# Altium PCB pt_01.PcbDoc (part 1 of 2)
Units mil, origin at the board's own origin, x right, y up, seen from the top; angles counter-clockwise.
Board outline 1456.69 x 1118.11 mil, 4 copper layers (Top Layer, med1, med2, Bottom Layer), stack 40.249 mil thick; 153 components, 173 nets, 567 pads, 147 vias.
Unrouted connection lines stored in the file: 22.
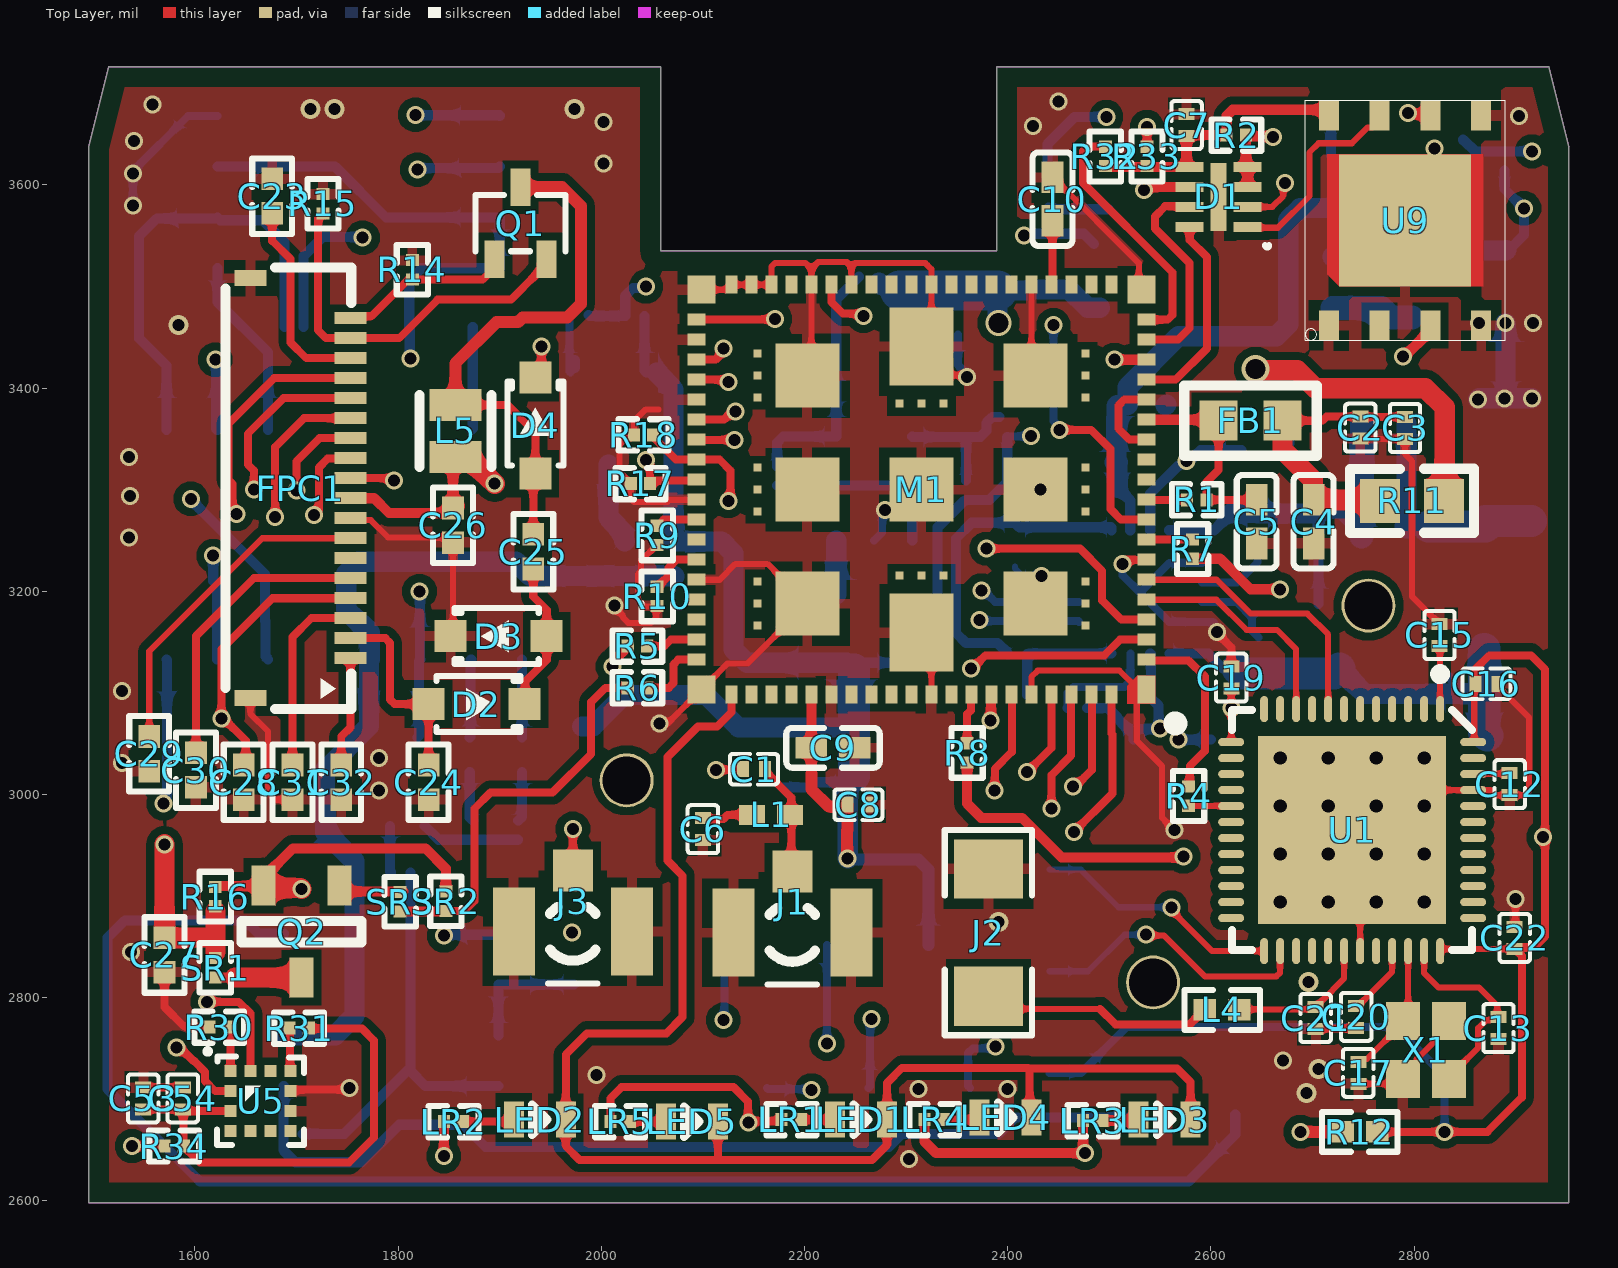
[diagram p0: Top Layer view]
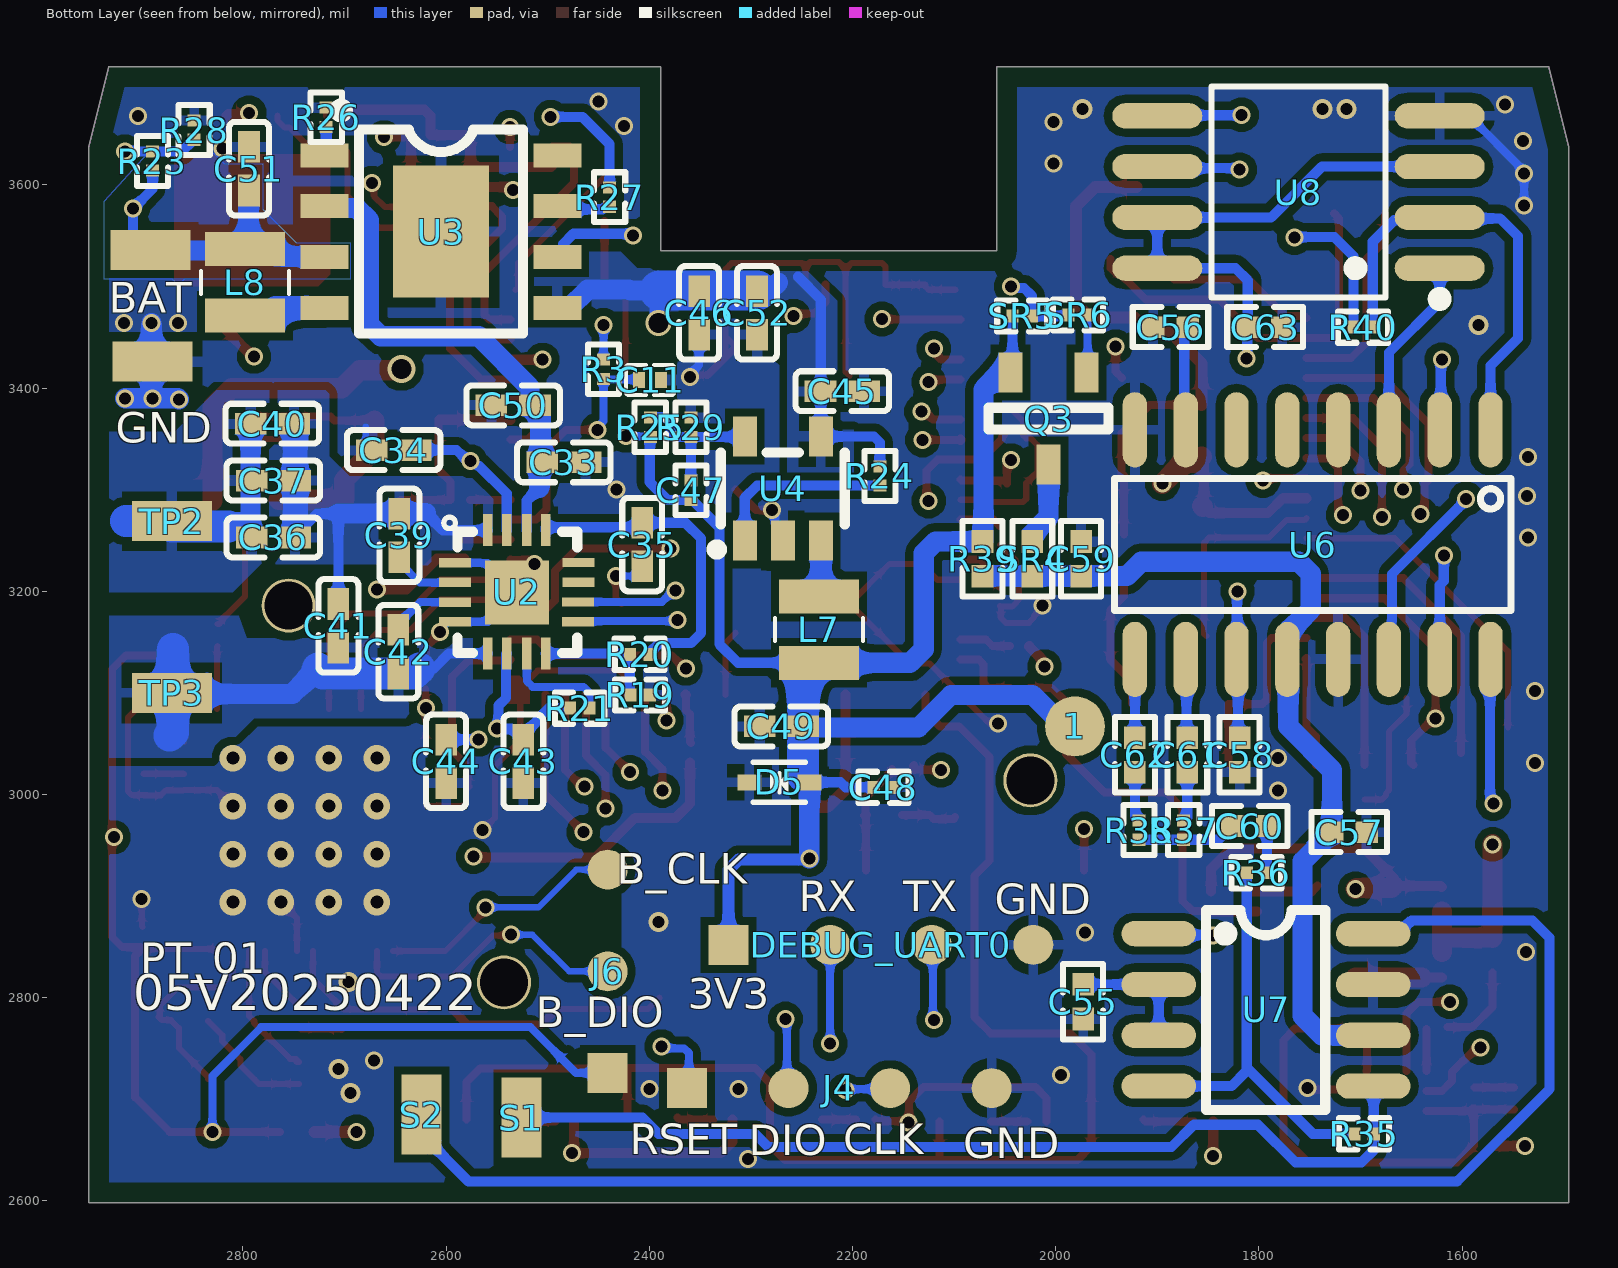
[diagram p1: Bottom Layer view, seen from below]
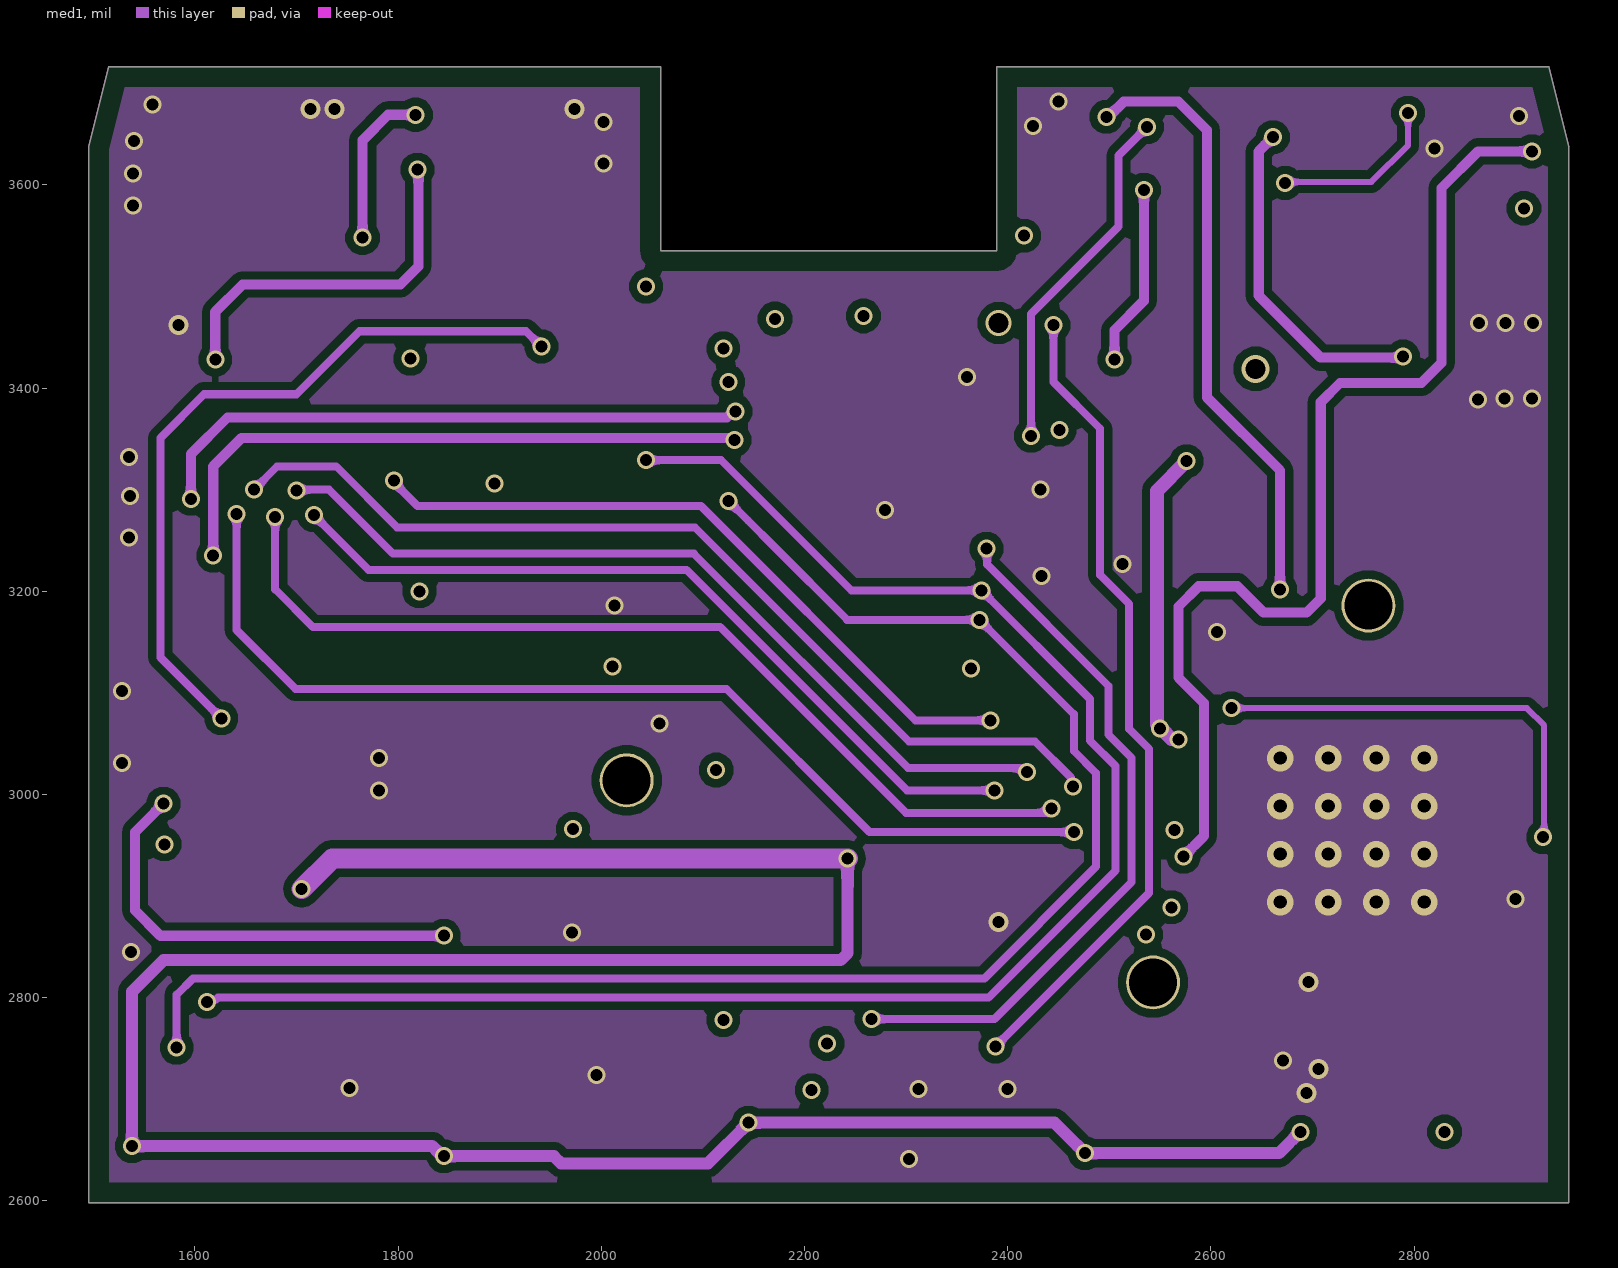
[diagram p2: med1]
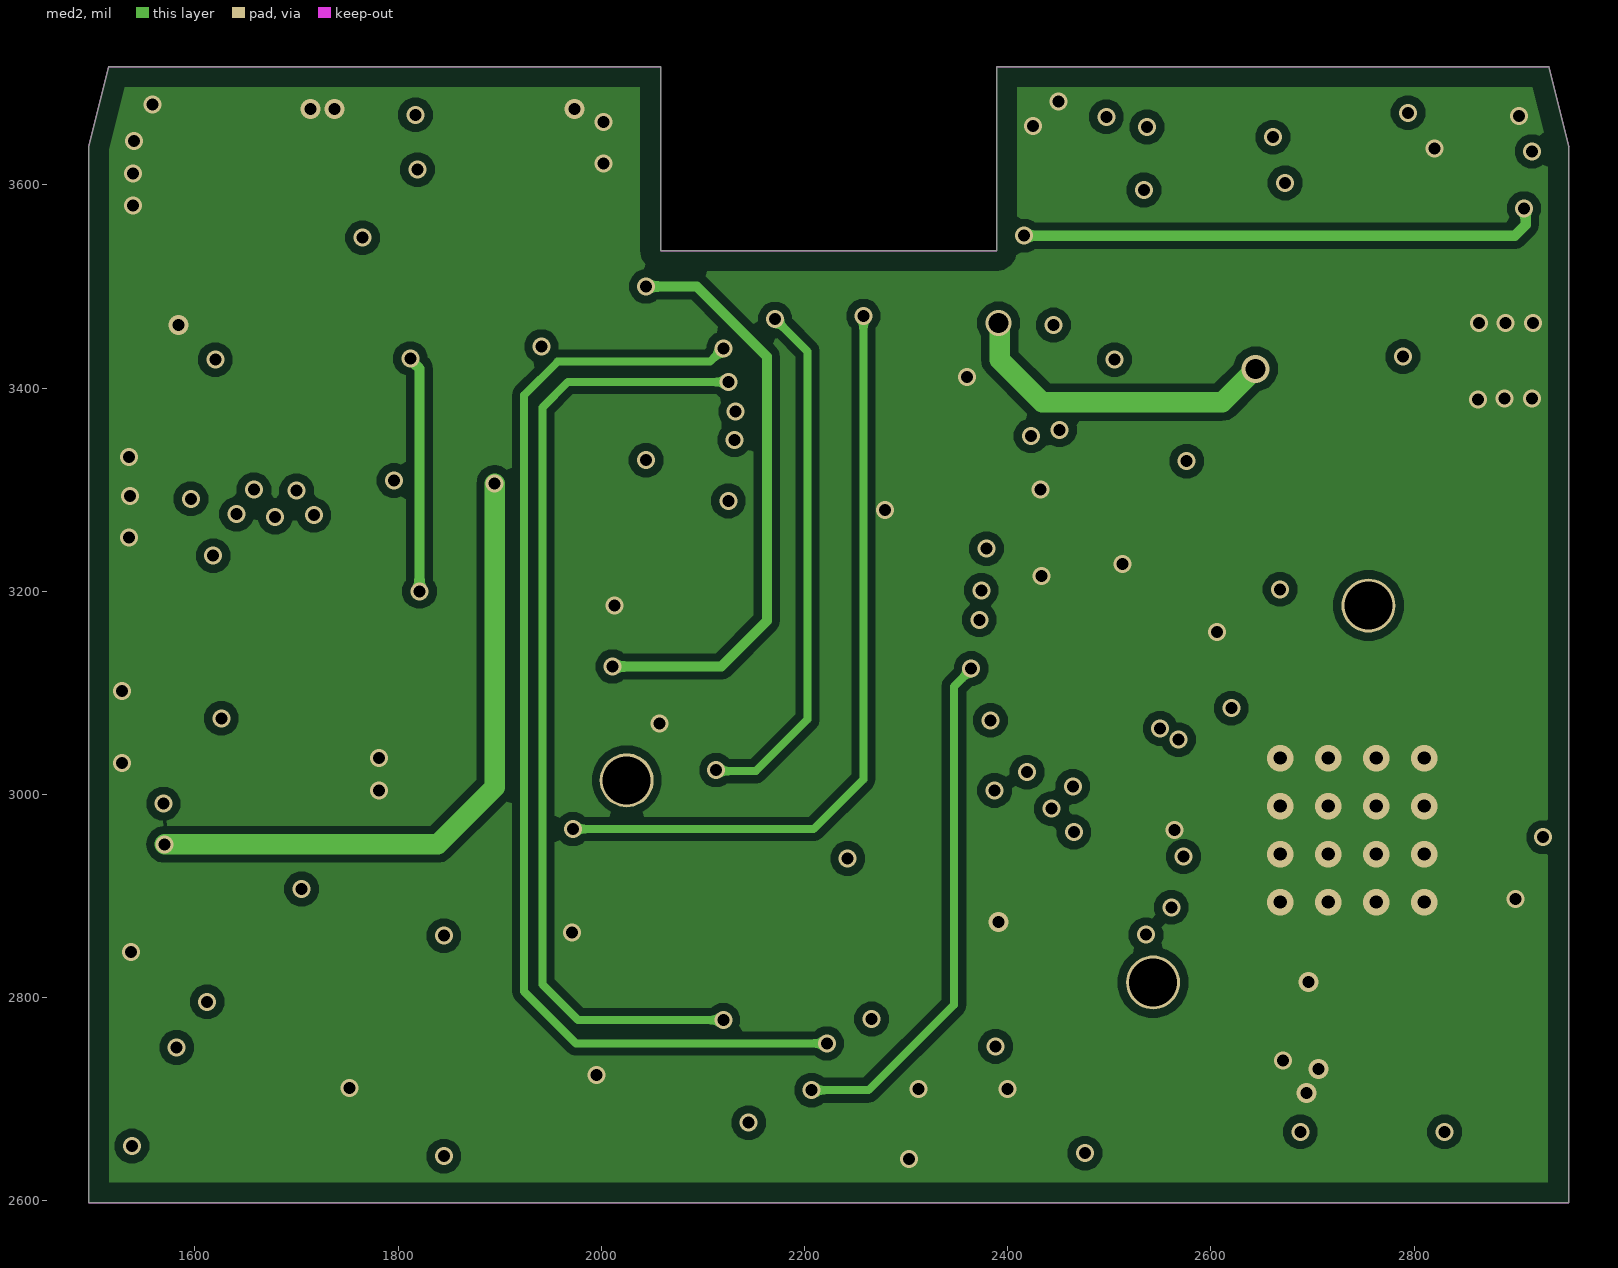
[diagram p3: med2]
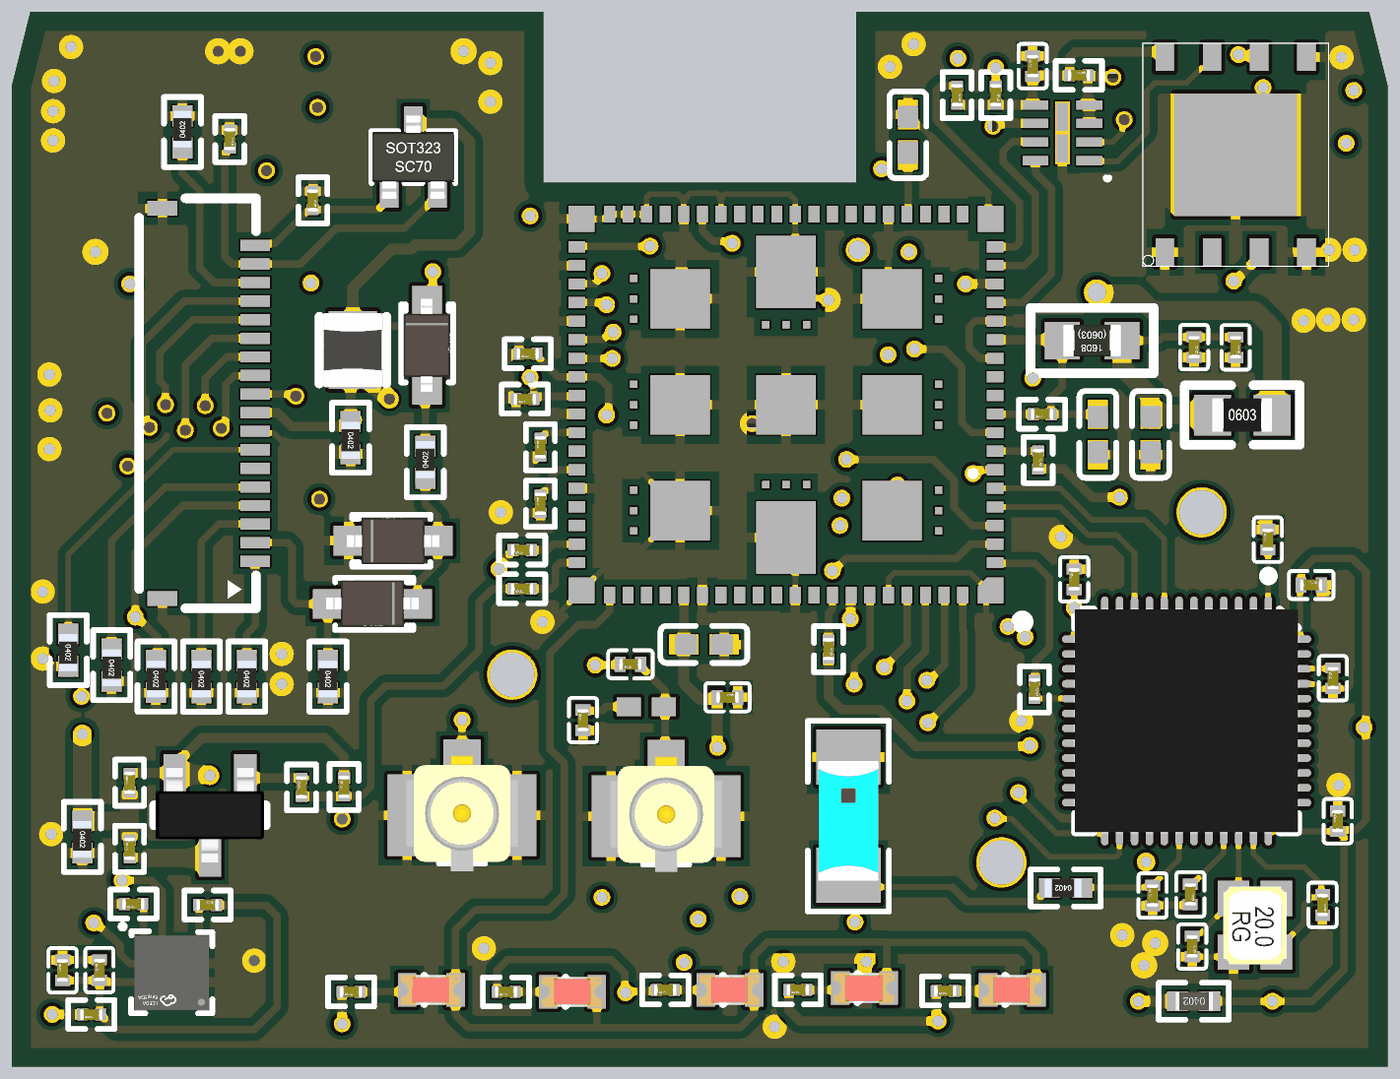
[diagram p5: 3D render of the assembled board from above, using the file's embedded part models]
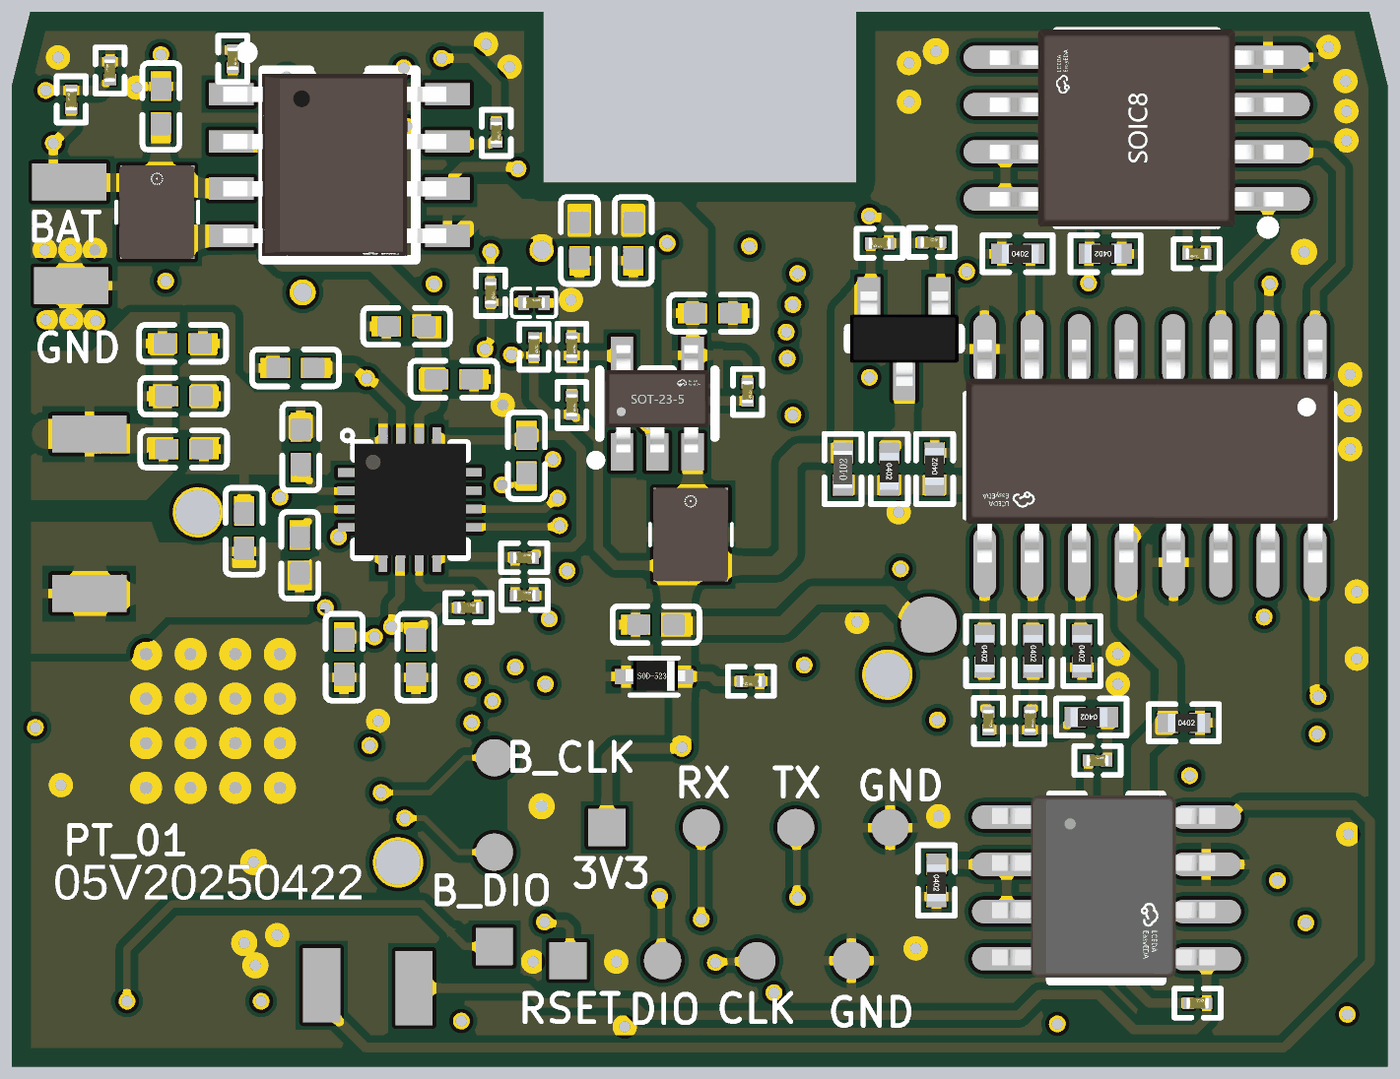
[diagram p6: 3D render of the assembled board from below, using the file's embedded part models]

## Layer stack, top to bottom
Top Solder: solder mask 0.4, Solder Resist, Dk 3.5
Top Layer: signal copper 1.4
Dielectric 1: dielectric 8.2839, FR-4, Dk 4.8
med1: signal copper 0.598
Dielectric 2: prepreg 19.685, PP-006, Dk 4.1
med2: signal copper 0.598
Dielectric2: dielectric 8.2839, FR-4, Dk 4.8
Bottom Layer: signal copper 1.4
Bottom Solder: solder mask 0.4, Solder Resist, Dk 3.5

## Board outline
1495.25,2598.41 1495.25,3637.78 1514.93,3716.52 2058.24,3716.52 2058.24,3535.42 2388.95,3535.42 2388.95,3716.52 2932.26,3716.52 2951.94,3637.78 2951.94,2598.41

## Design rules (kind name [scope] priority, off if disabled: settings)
Clearance Clearance_1 [InPolygon vs OnLayer('Keep-Out Layer')] p1: gap=19.68 ignorepadtopadclearanceinfootprint=TRUE except(0: Arc-Hole Track-Hole SMDPad-Hole THPad-Hole Via-Hole Fill-Hole Poly-Hole Region-Hole Text-Hole)
Clearance [All] p2: gap=8 ignorepadtopadclearanceinfootprint=TRUE except(0: Arc-Hole Track-Hole SMDPad-Hole THPad-Hole Via-Hole Fill-Hole Poly-Hole Region-Hole Text-Hole)
HoleToHoleClearance [All] p1: gap=2 allowstackedmicrovias=TRUE
MinimumSolderMaskSliver [All] p1: minsoldermaskwidth=2
PolygonConnect [All] p1: thpad.connectstyle=Relief thpad.reliefconductorwidth=10 thpad.reliefentries=4 thpad.polygonreliefangle="90 Angle" thpad.airgapwidth=10 smdpad.connectstyle=Relief smdpad.reliefconductorwidth=10 smdpad.reliefentries=4 smdpad.polygonreliefangle="90 Angle" smdpad.airgapwidth=10 via.connectstyle=Direct via.reliefconductorwidth=10 via.reliefentries=4 via.polygonreliefangle="90 Angle" via.airgapwidth=10
RoutingVias [All] p1: holewidth=11.81 width=19.68 viastyle="Through Hole" minholewidth=7.87 minwidth=11.81 maxholewidth=47.24 maxwidth=59.06
SilkToSilkClearance [All] p1: silktosilkclearance=2
SilkToSolderMaskClearance [IsPad] p1: minsilkscreentomaskgap=2 clearancetoexposedcopper=TRUE
SolderMaskExpansion [All] p1: expansion=4 istentingtop=FALSE
Width [All] p1: maxlimit=40 minlimit=6 preferedwidth=7.87
26 further rules are at their usual default settings.

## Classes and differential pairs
component class pt_01_speaker: C55 C56 C57 C58 C59 C60 C61 C62 C63 Q3 R35 R36 R37 R38 R39 R40 S1 S2 SR4 SR5 SR6 U6 U7 U8
component class pt_01_sensors: C53 C54 R30 R31 R34 U5
component class pt_01_power: 1 BAT C33 C34 C35 C36 C37 C39 C40 C41 C42 C43 C44 C45 C46 C47 C48 C49 C50 C51 C52 D5 GND L7 L8 R17 R18 R19 R20 R21 R23 R24 R25 R26 R27 R28 R29 TP2 TP3 U2 U3 U4
component class pt_01_nrf52832: C12 C13 C15 C16 C17 C19 C20 C21 C22 J2 J6 L4 R12 U1 X1
component class pt_01_main: C1 C2 C3 C4 C5 C6 C7 C8 C9 C10 C11 D1 DEBUG_UART0 FB1 J1 J3 J4 L1 LED1 LED2 LED3 LED4 LED5 LR1 LR2 LR3 LR4 LR5 M1 R1 R2 R3 R4 R5 R6 R7 R8 R9 R10 R11 R32 R33 U9
component class pt_01_display: C23 C24 C25 C26 C27 C28 C29 C30 C31 C32 D2 D3 D4 FPC1 L5 Q1 Q2 R14 R15 R16 SR1 SR2 SR3

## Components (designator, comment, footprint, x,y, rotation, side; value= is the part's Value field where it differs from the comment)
1 "TestPort" TESTPOINT 1981,3067 r90 bottom net-tie
BAT "" PIN 2891,3536 r0 bottom
C1 "39pF" C0201 2150.18,3025 r180 top
C2 "1.0µF" C0201 2747,3361 r270 top
C3 "1.0µF" C0201 2791,3360.82 r270 top
C4 "10µF" C0402 2701,3268.54 r270 top
C5 "10µF" C0402 2645,3268.54 r270 top
C6 "N.C." C0201 2100,2965.82 r90 top
C7 "10nF" C0201 2576,3658.82 r90 top
C8 "100nF" C0201 2253,2990 r0 top
C9 "4.7µF" C0402 2228,3046 r0 top
C10 "4.7µF" C0402 2444,3586 r90 top
C11 "100nF" C0201 2399.18,3408 r180 bottom
C12 "1.0µF" C0201 2894,3010.18 r90 top
C13 "12pF" C0201 2883,2770 r270 top
C15 "100nF" C0201 2825,3157 r90 top
C16 "4.7µF" C0201 2871,3109 r0 top
C17 "12pF" C0201 2745,2726 r270 top
C19 "100nF" C0201 2620,3115 r90 top
C20 "100pF" C0201 2743,2781.18 r270 top
C21 "0.8pF" C0201 2703,2780 r90 top
C22 "100nF" C0201 2899,2858.82 r90 top
C23 "1.0uF" RC_0402 1676,3589 r90 top
C24 "1.0uF" RC_0402 1830,3011.96 r270 top
C25 "4.7uF" RC_0402 1933,3239.04 r90 top
C26 "1.0uF" RC_0402 1854,3265 r270 top
C27 "4.7uF" RC_0402 1570,2842.04 r270 top
C28 "1.0uF" RC_0402 1648,3012 r270 top
C29 "1.0uF" RC_0402 1555,3040 r270 top
C30 "1.0uF" RC_0402 1601,3024 r270 top
C31 "1.0uF" RC_0402 1696,3011.96 r270 top
C32 "1.0uF" RC_0402 1744,3011.96 r270 top
C33 "10uF" C0402 2484,3327 r180 bottom
C34 "10uF" C0402 2651.54,3339 r0 bottom
C35 "1uF" C0402 2407,3246 r270 bottom
C36 "100nF" C0402 2770,3253 r180 bottom
C37 "47nF" C0402 2770,3309 r180 bottom
C39 "47nF" C0402 2646,3255 r270 bottom
C40 "33nF" C0402 2771,3365 r180 bottom
C41 "2.2nF" C0402 2706,3166 r90 bottom
C42 "47nF" C0402 2647,3140.54 r90 bottom
C43 "10uF" C0402 2524,3032.54 r270 bottom
C44 "100nF" C0402 2600,3032.54 r270 bottom
C45 "10uF" C0402 2210,3397 r0 bottom
C46 "100nF" C0402 2351,3474 r90 bottom
C47 "22pF" R0201 2359,3299.51 r270 bottom
C48 "100nF" R0201 2169.51,3007 r0 bottom
C49 "10uF" C0402 2270,3067 r180 bottom
C50 "10uF" C0402 2534,3383 r180 bottom
C51 "10uF" C0402 2794,3616 r270 bottom
C52 "4.7uF" C0402 2294,3474 r90 bottom
C53 "100nF" C0201 1549,2700.82 r90 top
C54 "4.7µF" C0201 1588,2701 r90 top
C55 "100nF" RC_0402 1973,2796.04 r270 bottom
C56 "100nF" RC_0402 1887,3460 r180 bottom
C57 "100nF" RC_0402 1711,2963 r180 bottom
C58 "1uF" RC_0402 1819,3039 r270 bottom
C59 "1uF" RC_0402 1975,3232 r90 bottom
C60 "10nF" RC_0402 1808.96,2969 r0 bottom
C61 "1uF" RC_0402 1870.5,3039 r270 bottom
C62 "1uF" RC_0402 1922,3039 r270 bottom
C63 "10nF" RC_0402 1793.96,3460 r0 bottom
D1 "TPD3F303DPVR" SON50P210X160X65_HS-9N 2607.54,3588.16 r180 top
D2 "RB551V-30" SOD-323_L1.7-W1.3-LS2.5-RD 1877,3089 r180 top
D3 "RB551V-30" SOD-323_L1.7-W1.3-LS2.5-RD 1899,3156 r0 top
D4 "RB551V-30" SOD-323_L1.7-W1.3-LS2.5-RD 1935,3363 r270 top
D5 "PESD5V0S1BB" SOD-523 2272,3012 r180 bottom value=LESD5D5.0CT1G
DEBUG_UART0 "NC" 2_54-4P#1 2322,2852 r90 bottom
FB1 "22R@100M/6A" 0603 2639,3368 r180 top
FPC1 "0.5K-HX-18PWB" FPC-SMD_18P-P0.50_HDGC_0.5K-HX-18PWB 1703.79,3301.47 r270 top
GND "" PIN 2889,3426 r0 bottom
J1 "BWU.FL-IPEX1" "COAXIAL RF U.FL-R-SMT-1" 2188,2864 r180 top value="MHF I Receptacle"
J2 "2PIN" ANT-SMD-2_L3.2-W1.6-C504002 2381,2864 r90 top
J3 "BWU.FL-IPEX1" "COAXIAL RF U.FL-R-SMT-1" 1971.93,2865 r180 top value="MHF I Receptacle"
J4 "4PIN" 2_54-4P#1 2363,2711 r90 bottom
J6 "4PIN" 2_54-4P#2 2441,2726 r0 bottom
L1 "N.C." INDC1005X04L_NC 2167,2980 r180 top
L4 "3.9nH" RC_0402 2611,2788 r180 top
L5 "10uH" IND-SMD_L2.0-W1.2_FTC201210S 1856.31,3357.9 r90 top
L7 "2.2uH(20%)_3A" IND-SMD_L2.5-W2.0-VLS252012CX-150M 2233,3162.32 r270 bottom
L8 "2.2uH(20%)_3A" IND-SMD_L2.5-W2.0-VLS252012CX-150M 2798,3504 r270 bottom
LED1 "LED" EVE_0603_LED 2255.59,2680 r0 top
LED2 "LED" EVE_0603_LED 1939.41,2680 r0 top
LED3 "LED" EVE_0603_LED 2554.41,2680 r0 top
LED4 "LED" EVE_0603_LED 2398,2682 r0 top
LED5 "LED" EVE_0603_LED 2089,2678 r0 top
LR1 "1K" R0201 2187,2680 r180 top
LR2 "1K" R0201 1854.49,2678 r180 top
LR3 "1K" R0201 2483.49,2679 r180 top
LR4 "1K" R0201 2327.49,2680 r180 top
LR5 "1K" R0201 2018.49,2678 r180 top
M1 "nRF9151-LACAA0A" LGA50P1210X1110X130-113N 2315,3300 r90 top
Q1 "SI1308EDL" SOT-323-3_L2.0-W1.3-P1.30-LS2.1-BR 1920.41,3562.35 r270 top
Q2 "FH3415S" SOT-23 1705,2865 r180 top
Q3 "FH3415S" SOT-23 2007,3370 r0 bottom
R1 "10k" R0201 2586,3290 r180 top
R2 "4.7K" R0201 2625,3649 r0 top
R3 "1k" R0201 2445,3418.51 r270 bottom
R4 "0R" R0201 2578,2998.49 r270 top
R5 "0R" R0201 2035.49,3146 r180 top
R6 "0R" R0201 2035.49,3105 r180 top
R7 "0R" R0201 2582,3241.51 r270 top
R8 "0R" R0201 2360,3041 r270 top
R9 "1M0" R0201 2055,3255 r90 top
R10 "1M0" R0201 2055,3195 r90 top
R11 "0R" R0603 2798,3289 r0 top
R12 "0R" R0402 2746.51,2668 r180 top
R14 "10K" R0201 1814,3516.49 r270 top
R15 "3R" R0201 1726,3581.51 r270 top
R16 "N.C." R0201 1620,2899.51 r90 top
R17 "NC" R0201 2038.49,3306 r180 top
R18 "NC" R0201 2041.51,3354 r180 top
R19 "0R" R0201 2409,3098 r180 bottom
R20 "NC" R0201 2409.49,3138 r180 bottom
R21 "220R" R0201 2468.49,3085 r180 bottom
R23 "100K" R0201 2889,3623.51 r90 bottom
R24 "10K" R0201 2173,3313.51 r270 bottom
R25 "680K(1%)" R0201 2399,3361.51 r270 bottom
R26 "1K" R0201 2718,3666.51 r270 bottom
R27 "2K" R0201 2439,3588 r270 bottom
R28 "100K" R0201 2848,3654 r90 bottom
R29 "150K(1%)" R0201 2359,3361.51 r270 bottom
R30 "0R" R0201 1624,2771 r180 top
R31 "0R" R0201 1702.49,2770 r0 top
R32 "0R" R0201 2496,3628 r270 top
R33 "NC" R0201 2537,3628 r270 top
R34 "0R" R0201 1579.51,2654 r180 top
R35 "51K" R0201 1696.51,2666 r180 bottom
R36 "10K" R0201 1802.49,2923 r180 bottom
R37 "1K" R0201 1874,2965 r270 bottom
R38 "1K" R0201 1918,2965 r270 bottom
R39 "N.C." R0402 2072,3232 r90 bottom
R40 "100R" R0201 1697.49,3460 r0 bottom
S1 "" PIN 2526,2682 r270 bottom
S2 "" PIN 2624,2685 r270 bottom
SR1 "0R" R0201 1620,2829.51 r90 top
SR2 "10K" R0201 1847,2895 r90 top
SR3 "10K" R0201 1802,2894.51 r90 top
SR4 "0R" RC_0402 2023,3232 r270 bottom
SR5 "10K" R0201 2033,3471 r0 bottom
SR6 "10K" R0201 1978,3472 r180 bottom
TP2 "" PIN 2870,3269 r0 bottom
TP3 "" PIN 2870,3100 r0 bottom
U1 "nRF52832-QFAB" QFN40P600X600X90-48N 2739,2965 r270 top
U2 "NU1680" QFN16-3*3 2530.55,3199.42 r90 bottom
U3 "ETA9697E8A" ESOP-8_L4.9-W3.9-P1.27-LS6.0-BL-EP 2605,3554 r270 bottom
U4 "SY8088AAC" SOT-23-5_L3.0-W1.7-P0.95-LS2.8-BR 2268.6,3301.18 r270 bottom
U5 "QMA6100P" LGA-12_L2.0-W2.0-P0.50-TL_QMA6100 1664.53,2698.16 r0 top
U6 "KT804C" SO16M1 1747.07,3245.88 r0 bottom
U7 "FM8002A" SOP-8_L4.9-W3.9-P1.27-LS6.0-BL 1793,2788 r270 bottom
U8 "W25Q16JVSSIQ" SOIC-8_L5.3-W5.3-P1.27-LS8.0-BL 1761.02,3593 r90 bottom
U9 "SIM-ESIM-CARD_5X6" SIM-MFF2 2791,3565 r90 top
X1 "32MHz" BT-XTAL_2016 2811.46,2748.36 r270 top

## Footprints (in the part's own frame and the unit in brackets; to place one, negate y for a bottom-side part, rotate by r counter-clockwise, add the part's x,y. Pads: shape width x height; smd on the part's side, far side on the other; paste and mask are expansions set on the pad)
2_54-4P#1 [mm]
  rect 1x1 smd: 1(0,0)
  round 1 smd: 2(0,-2.54) 3(0,-5.08) 4(0,-7.62)
2_54-4P#2 [mm]
  rect 1x1 smd: 1(0,0)
  round 1 smd: 2(0,-2.54) 3(0,-5.08)
0603 [mm] "SMD, 0603"
  rect 0.95x1 smd: 1(-0.8,0) 2(0.8,0)
  silkscreen extent -1.66,-0.88 1.66,0.88, body extent -0.77,-0.43 0.77,0.43, height 0.45
ANT-SMD-2_L3.2-W1.6-C504002 [mm]
  rect 1.485x1.728 smd: 1(-1.593,-0.001) 2(1.593,0.001)
  silkscreen extent -2.56,-1.09 2.56,1.09, body extent -1.74,-0.81 1.48,0.81, height 0.62
BT-XTAL_2016 [mm]
  rect 0.95x0.85 smd: 1(-0.725,-0.575) 2(0.725,-0.575) 3(0.725,0.575) 4(-0.725,0.575)
  body extent -1.05,-0.85 1.05,0.85, height 0.56
C0201 [mm]
  rect 0.3x0.4 smd paste+0 mask+0.102: 1(-0.275,0) 2(0.275,0)
  silkscreen extent -0.6,-0.38 0.6,0.38, body extent -0.3,-0.15 0.3,0.15, height 0.31
C0402 [mm]
  rect 0.79x0.54 smd paste-100 mask+0.051: 1(-0.545,0) 2(0.545,0)
  silkscreen extent -1.17,-0.5 1.17,0.5, body extent -0.5,-0.25 0.5,0.25, height 0.5
"COAXIAL RF U.FL-R-SMT-1" [mm]
  rect 1x1.05 smd: 1(0,-1.525)
  rect 1.05x2.2 smd: 2(-1.475,0) 2(1.475,0)
  Top Layer pour cut-out: 0.85,1.3 -0.85,1.3 -0.85,-1.525 0.85,-1.525
  silkscreen extent -0.62,-0.62 0.62,1.3, body extent -1.5,-1.6 1.5,1.5, height 1.25
ESOP-8_L4.9-W3.9-P1.27-LS6.0-BL-EP [mm]
  rect 0.6x1.2 smd: 1(-1.905,-2.908) 2(-0.635,-2.908) 3(0.635,-2.908) 4(1.905,-2.908) 5(1.905,2.908) 6(0.635,2.908) 7(-0.635,2.908) 8(-1.905,2.908)
  rect 3.3x2.4 smd: 9(0,0)
  silkscreen extent -3.2,-2.67 2.55,2.05, body extent -2.45,-3.13 2.45,2.87, height 1.75
EVE_0603_LED [mm]
  rect 0.5x0.9 smd: A(-0.65,0) K(0.65,0)
  silkscreen extent -0.19,-0.38 0.19,0.38, body extent -0.81,-0.4 0.79,0.4, height 0.6
FPC-SMD_18P-P0.50_HDGC_0.5K-HX-18PWB [mm]
  rect 0.3x0.8 smd paste+0 mask+0.05: 1(4.25,1.25) 2(3.75,1.25) 3(3.25,1.25) 4(2.75,1.25) 5(2.25,1.25) 6(1.75,1.25) 7(1.25,1.25) 8(0.75,1.25) 9(0.25,1.25) 10(-0.25,1.25) 11(-0.75,1.25) 12(-1.25,1.25) 13(-1.75,1.25) 14(-2.25,1.25) 15(-2.75,1.25) 16(-3.25,1.25) 17(-3.75,1.25) 18(-4.25,1.25)
  rect 0.4x0.8 smd paste+0 mask+0.05: 19(-5.25,-1.25) 20(5.25,-1.25)
  silkscreen extent -5.52,-1.87 5.52,1.27, body extent -5.46,-1.9 5.46,1.27, height 1
IND-SMD_L2.0-W1.2_FTC201210S [mm]
  rect 0.8x1.3 smd: 1(-0.65,0) 2(0.65,0)
  silkscreen extent -0.9,-0.9 0.9,0.9, body extent -1,-0.8 1,0.8, height 0.95
IND-SMD_L2.5-W2.0-VLS252012CX-150M [mm]
  rect 0.85x2 smd: 1(-0.83,0) 2(0.83,0)
  silkscreen extent -0.29,-1.1 0.29,1.1, body extent -1.26,-1.02 1.26,1, height 1.22
INDC1005X04L_NC [mm]
  rect 0.65x0.5 smd: 1(-0.475,0) 2(0.475,0)
LGA50P1210X1110X130-113N [mm]
  rect 0.7x0.45 smd paste+0 mask-5: 1(-5,-5.625)
  rect 0.3x0.45 smd mask+0.05: 2(-4.25,-5.625) 3(-3.75,-5.625) 4(-3.25,-5.625) 5(-2.75,-5.625) 6(-2.25,-5.625) 7(-1.75,-5.625) 8(-1.25,-5.625) 9(-0.75,-5.625) 10(-0.25,-5.625) 11(0.25,-5.625) 12(0.75,-5.625) 13(1.25,-5.625) 14(1.75,-5.625) 15(2.25,-5.625) 16(2.75,-5.625) 17(3.25,-5.625) 18(3.75,-5.625) 19(4.25,-5.625) 42(4.25,5.625) 43(3.75,5.625) 44(3.25,5.625) 45(2.75,5.625) 46(2.25,5.625) 47(1.75,5.625) 48(1.25,5.625) 49(0.75,5.625) 50(0.25,5.625) 51(-0.25,5.625) 52(-0.75,5.625) 53(-1.25,5.625) 54(-1.75,5.625) 55(-2.25,5.625) 56(-2.75,5.625) 57(-3.25,5.625) 58(-3.75,5.625) 59(-4.25,5.625)
  rect 0.7x0.7 smd mask+0.05: 20(5,-5.5) 41(5,5.5) 60(-5,5.5)
  rect 0.45x0.3 smd mask+0.05: 21(5.125,-4.75) 22(5.125,-4.25) 23(5.125,-3.75) 24(5.125,-3.25) 25(5.125,-2.75) 26(5.125,-2.25) 27(5.125,-1.75) 28(5.125,-1.25) 29(5.125,-0.75) 30(5.125,-0.25) 31(5.125,0.25) 32(5.125,0.75) 33(5.125,1.25) 34(5.125,1.75) 35(5.125,2.25) 36(5.125,2.75) 37(5.125,3.25) 38(5.125,3.75) 39(5.125,4.25) 40(5.125,4.75) 61(-5.125,4.75) 62(-5.125,4.25) 63(-5.125,3.75) 64(-5.125,3.25) 65(-5.125,2.75) 66(-5.125,2.25) 67(-5.125,1.75) 68(-5.125,1.25) 69(-5.125,0.75) 70(-5.125,0.25) 71(-5.125,-0.25) 72(-5.125,-0.75) 73(-5.125,-1.25) 74(-5.125,-1.75) 75(-5.125,-2.25) 76(-5.125,-2.75) 77(-5.125,-3.25) 78(-5.125,-3.75) 79(-5.125,-4.25) 80(-5.125,-4.75)
  rect 0.2x0.2 smd mask+0.05: 81(-3.4,-4.1) 82(-2.85,-4.1) 83(-2.3,-4.1) 84(-0.55,-4.1) 85(0,-4.1) 86(0.55,-4.1) 87(2.3,-4.1) 88(2.85,-4.1) 89(3.4,-4.1) 90(2.15,-0.55) 91(2.15,0) 92(2.15,0.55) 93(3.4,4.1) 94(2.85,4.1) 95(2.3,4.1) 96(0.55,4.1) 97(0,4.1) 98(-0.55,4.1) 99(-2.3,4.1) 100(-2.85,4.1) 101(-3.4,4.1) 102(-2.15,0.55) 103(-2.15,0) 104(-2.15,-0.55)
  rect 1.6x1.6 smd mask+0.05: 105(-2.85,-2.85) 106(0,-2.85) 107(2.85,-2.85) 109(2.85,2.85) 110(0,2.85) 111(-2.85,2.85) 113(0,0)
  rect 1.95x1.6 smd mask+0.05: 108(3.575,0) 112(-3.575,0)
  Top Layer region: -5.35,-5.15 -5.35,-5.85 -4.65,-5.85 -4.65,-5.4 -4.9,-5.15
  silkscreen extent -5.99,-6.5 -5.69,-6.2, body extent -5.6,-6.1 5.6,6.1, height 1.21
LGA-12_L2.0-W2.0-P0.50-TL_QMA6100 [mm]
  rect 0.3x0.3 smd paste+0 mask+0.05: 1(-0.75,0.75) 2(-0.75,0.25) 3(-0.75,-0.25) 4(-0.75,-0.75) 5(-0.25,-0.75) 6(0.25,-0.75) 7(0.75,-0.75) 8(0.75,-0.25) 9(0.75,0.25) 10(0.75,0.75) 11(0.25,0.75) 12(-0.25,0.75)
  silkscreen extent -1.38,-1.09 1.09,1.3, body extent -1,-1 1,1, height 0.96
PIN [mm]
  rect 2x1 smd: 1(0,0)
  body extent -1.02,-0.51 1.02,0.51, height 0.3
QFN16-3*3 [mm]
  rect 0.23x0.8 smd: 1(0.728,1.535) 2(0.24,1.541) 3(-0.259,1.538) 4(-0.747,1.535) 9(-0.748,-1.538) 10(-0.252,-1.539) 11(0.242,-1.541) 12(0.732,-1.541)
  rect 0.8x0.23 smd: 5(-1.542,0.724) 6(-1.539,0.247) 7(-1.539,-0.252) 8(-1.543,-0.726) 13(1.543,-0.726) 14(1.543,-0.252) 15(1.543,0.249) 16(1.542,0.721)
  rect 1.6x1.6 smd: 17(-0.017,-0.013)
  silkscreen extent -1.52,-1.52 1.87,1.82, body extent -1.49,-1.52 1.51,1.49, height 0.9
QFN40P600X600X90-48N [mm]
  oval 0.65x0.2 smd: 1(-3.025,2.2) 2(-3.025,1.8) 3(-3.025,1.4) 4(-3.025,1) 5(-3.025,0.6) 6(-3.025,0.2) 7(-3.025,-0.2) 8(-3.025,-0.6) 9(-3.025,-1) 10(-3.025,-1.4) 11(-3.025,-1.8) 12(-3.025,-2.2) 25(3.025,-2.2) 26(3.025,-1.8) 27(3.025,-1.4) 28(3.025,-1) 29(3.025,-0.6) 30(3.025,-0.2) 31(3.025,0.2) 32(3.025,0.6) 33(3.025,1) 34(3.025,1.4) 35(3.025,1.8) 36(3.025,2.2)
  oval 0.2x0.65 smd: 13(-2.2,-3.025) 14(-1.8,-3.025) 15(-1.4,-3.025) 16(-1,-3.025) 17(-0.6,-3.025) 18(-0.2,-3.025) 19(0.2,-3.025) 20(0.6,-3.025) 21(1,-3.025) 22(1.4,-3.025) 23(1.8,-3.025) 24(2.2,-3.025) 37(2.2,3.025) 38(1.8,3.025) 39(1.4,3.025) 40(1,3.025) 41(0.6,3.025) 42(0.2,3.025) 43(-0.2,3.025) 44(-0.6,3.025) 45(-1,3.025) 46(-1.4,3.025) 47(-1.8,3.025) 48(-2.2,3.025)
  rect 4.7x4.7 smd: 49(0,0)
  silkscreen extent -4.02,-3 3,3, body extent -3.02,-3.02 3.02,3.02, height 0.86
R0201 [mil]
  rect 11.93x12.76 smd paste-3937.01 mask+2: 1(-9.51,0) 2(9.51,0)
  silkscreen extent -24,-15 24,15, body extent -12,-6 12,6, height 12
R0402 [mm]
  rect 0.566x0.54 smd paste-100 mask+0.051: 1(-0.433,0) 2(0.433,0)
  silkscreen extent -0.94,-0.5 0.94,0.5, body extent -0.52,-0.25 0.48,0.25, height 0.35
R0603 [mm]
  rect 1x1.1 smd paste+0 mask+0.102: 1(-0.8,0) 2(0.8,0)
  silkscreen extent -1.55,-0.8 1.55,0.81, body extent -0.8,-0.45 0.8,0.45, height 0.5
RC_0402 [mm]
  rect 0.566x0.54 smd paste-100 mask+0.051: 1(-0.433,0) 2(0.433,0)
  silkscreen extent -0.94,-0.5 0.94,0.5, body extent -0.43,-0.25 0.57,0.25, height 0.34
SIM-MFF2 [mm]
  rect 0.75x0.5 smd: C1(2.625,1.905) C2(2.625,0.635) C3(2.625,-0.635) C4(2.625,-1.905) C5(-2.625,1.905) C6(-2.625,0.635) C7(-2.625,-0.635) C8(-2.625,-1.905)
  rrect0% 3.3x3.3 smd: C9(0,0)
  Top Layer region: -1.65,1.65 -1.35,1.95 1.65,1.95 1.65,-1.95 -1.65,-1.95 -1.65,1.65
  silkscreen extent -3,-2.5 3,2.5, body extent -3.05,-2.54 3.05,2.54, height 2
SO16M1 [mil]
  oval 24x74 smd: 1(-175.07,-113.12) 2(-125.07,-113.12) 3(-75.07,-113.12) 4(-25.07,-113.12) 5(24.93,-113.12) 6(74.93,-113.12) 7(124.93,-113.12) 8(174.93,-113.12) 9(174.93,112.88) 10(124.93,112.88) 11(74.93,112.88) 12(24.93,112.88) 13(-25.07,112.88) 14(-75.07,112.88) 15(-125.07,112.88) 16(-175.07,112.88)
  silkscreen extent -195,-65 195,65, body extent -195,-123 195,113, height 75
SOD-323_L1.7-W1.3-LS2.5-RD [mm]
  rect 0.8x0.8 smd: 1(-1.2,0) 2(1.2,0)
  silkscreen extent -1.1,-0.7 1,0.7, body extent -1.25,-0.64 1.25,0.61, height 0.95
SOD-523 [mm]
  rect 0.6x0.4 smd: 1(-0.75,0) 2(0.75,0)
  silkscreen extent -0.65,-0.5 0.65,0.5, body extent -0.76,-0.38 0.84,0.42, height 0.65
SOIC-8_L5.3-W5.3-P1.27-LS8.0-BL [mm]
  oval 0.63x2.25 smd: 1(-1.905,-3.53) 2(-0.635,-3.53) 3(0.635,-3.53) 4(1.905,-3.53) 5(1.905,3.53) 6(0.635,3.53) 7(-0.635,3.53) 8(-1.905,3.53)
  silkscreen extent -2.82,-3.68 2.64,2.18, body extent -2.65,-3.95 2.65,3.95, height 2.07
SON50P210X160X65_HS-9N [mm]
  rect 0.7x0.25 smd mask+0.05: 1(-0.725,0.75) 2(-0.725,0.25) 3(-0.725,-0.25) 4(-0.725,-0.75) 5(0.725,-0.75) 6(0.725,-0.25) 7(0.725,0.25) 8(0.725,0.75)
  rect 0.4x1.7 smd paste-2 mask+0.05: 9(0,0)
  rect 0.3x0.75 on Top Paste: ""(0,0.425) ""(0,-0.425)
  silkscreen extent -1.26,1.2 -1.16,1.26, body extent -0.85,-1.1 0.85,1.1, height 0.65
SOP-8_L4.9-W3.9-P1.27-LS6.0-BL [mm]
  oval 0.63x1.865 smd: 1(-1.905,-2.682) 2(-0.635,-2.682) 3(0.635,-2.682) 4(1.905,-2.682) 5(1.905,2.682) 6(0.635,2.682) 7(-0.635,2.682) 8(-1.905,2.682)
  silkscreen extent -2.5,-1.5 2.5,1.48, body extent -2.49,-3.08 2.41,2.92, height 1.5
SOT-23 [mm] "SOT-23-3"
  rect 0.6x1 smd: 1(-0.95,-1.15) 2(0.95,-1.15) 3(0,1.15)
  silkscreen extent -1.5,-0.27 1.5,0.27, body extent -1.46,-1.28 1.46,1.27, height 0.99
SOT-23-5_L3.0-W1.7-P0.95-LS2.8-BR [mm]
  rect 1x0.6 smd: 1(1.3,-0.95) 2(1.3,0) 3(1.3,0.95) 4(-1.3,0.95) 5(-1.3,-0.95)
  silkscreen extent -0.9,-1.78 1.65,1.55, body extent -1.57,-1.39 1.32,1.39, height 1.2
SOT-323-3_L2.0-W1.3-P1.30-LS2.1-BR [mm]
  rect 0.936x0.5 smd: 1(0.898,-0.65) 2(0.898,0.65) 3(-0.898,0)
  silkscreen extent -0.7,-1.13 0.7,1.13, body extent -1.12,-1.1 1.12,1.1, height 1.1
TESTPOINT [mm]
  round 1.5 smd: 1(0,0)

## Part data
BAT GND S1 S2 TP2 TP3: library part Testpoint
C1: library part C0201-39p, "Capacitor, NP0, ±1%, 25V", Manufacturer=Murata, Manufacturer Part Number=GRM0335C1E390FA01, Part number IPS=00000001668, Part number NEMS=100200039, Part number Norautron=N.A.
C2 C3: library part C0201-1µ0-10V-X5R-GRM033R61A105ME15, "Capacitor, X5R, ±20%, 10V", Manufacturer=Murata, Manufacturer Part Number=GRM033R61A105ME15, Part number IPS=N.A., Part number NEMS=100200545, Supplier Part Number 1=490-13226-1-ND
C4 C5: library part C0603-10µ-10V-X6S-GRM188C81A106MA73, "Capacitor, Ceramic, 10µF 10V X6S 0603,±20%", Manufacturer=Murata, Manufacturer Part Number=GRM188C81A106MA73, Part number IPS=N.A., Part number NEMS=100200520, Supplier Part Number 1=490-7197-2-ND
C6: library part C0201-N.C., "Not mounted", Manufacturer=N.A., Part number NEMS=100200001
C7: library part C0201-10n, "Capacitor, X7R, ±10%", Manufacturer=N.A., Part number IPS=00000003480, Part number NEMS=100200067, Part number Norautron=26621779
C8 C11 C53: library part C0201-100n, "Capacitor, X5R, ±10%", Manufacturer=N.A., Part number IPS="00000001248, 00000002505", Part number NEMS=100200078, Part number Norautron=262071862
C9 C10 C54: library part C0402-4µ7-10V-X5R, "Capacitor, X5R, 10V", Manufacturer=Murata, Manufacturer Part Number=GRM155R61A475MEAAD, Part number IPS=N.A., Part number NEMS=100200415, Supplier Part Number 1=490-14306-1-ND
C12: library part C0603-1µ0, "Capacitor, X7R, ±10%"
C13 C17: library part C0402-12p, "Capacitor, NP0, ±2%"
C15 C19 C22: library part C0402-100n, "Capacitor, X7R, ±10%"
C16: library part C0603-4µ7, "Capacitor, X5R, ±10%"
C20: library part C0402-100p, "Capacitor, NP0, ±5%"
C21: library part C0402-0.8p, "Capacitor, NP0, ±5%"
C23 C24 C25 C26 C27 C28 C29 C30 C31 C32 C45 C46 C47 C48 C49 C50 C51 C52 C55 C56 C57 C58 C59 C60 C61 C62 C63: library part CT, "CT"
C33 C34 C35 C43 C44: library part cap, "CT"
C36 C37 C39 C40 C41 C42: library part cap, "0402"
D1: "ESD Protection and EMI Filter for SIM Card Interface", Manufacturer="Texas Instruments", Part number IPS=N.A., Part number NEMS=101900729, Supplier Part Number 1=296-28299-1-ND
D2 D3 D4: library part MBR0530_C5204746, Forward Voltage (Vf@If)=500mV@500mA, JLCPCB Part Class="Extended Part", LCSC Part Name="电压:30V 电流:500mA", Manufacturer=TWGMC(台湾迪嘉), Manufacturer Part=MBR0530, Rectified Current=500mA, Reverse Leakage Current (Ir)=130uA, Reverse Voltage (Vr)=30V
D5: library part DIODE_BI_DIR, Part Number=ES31320020000000
DEBUG_UART0: library part 4PIN
FB1: library part FB0603-22R@100MHz-6000mA, "Ferrite Bead, 22 Ohm @ 100MHz, 6000mA, 8 mOhm Max;BLM18SD220SN1Ds", Manufacturer=Murata, Manufacturer Part Number=BLM18SD220SN1D, Part number IPS=N.A., Supplier Part Number 1=490-15633-2-ND
FPC1: JLCPCB Part Class=扩展库, LCSC Part Name="翻盖式 双侧触点/上下接 P数:18P 间距:0.5mm", Manufacturer=HDGC(华德共创), Operating Temperature Range=-55℃~+85℃
J1 J3: library part 20279-001E-03, "Ultraminiature Coaxial Connector, 50 Ohm, SMD", Manufacturer=Wellshow, Part number IPS=00000004436, Part number NEMS=100500636, Part number Norautron=N.A.
L1: library part L0402-N.C., "Not mounted", Manufacturer=N.A., Part number NEMS=100300037
L4: library part L0402-3n9, "High frequency chip inductor ±5%"
L5: library part AFE201610S100MBT, DC Resistance (DCR)=483mΩ, LCSC Part Name="10µH ±20%", Manufacturer=Magnetsyc(元磁), Rated Current=1A, Saturation Current (Isat)=1.4A, Tolerance=±20%
L7: library part L, "FTC252012S2R2MBCA"
L8: library part L, "L"
LR1 LR2 LR3 LR4 LR5 R4 R5 R6 R7 R8 R11 R12 R16 R30 R31 R32 R33 R34 R39: library part R, BOM_Manufacturer=YAGEO, BOM_Manufacturer Part=AC0603JR-074K7L
M1: "Low power System-in-Package with integrated LTE-M/NB-IoT modem and GPS", Manufacturer="Nordic Semiconductor", Part number IPS=N.A.
Q1: Continuous Drain Current (Id)=1.4A, Drain Source On Resistance (RDS(on)@Vgs,Id)=150mΩ@4.5V,0.5A, Drain Source Voltage (Vdss)=30V, Gate Threshold Voltage (Vgs(th)@Id)=1.5V@250uA, Input Capacitance (Ciss@Vds)=146pF@15V, JLCPCB Part Class="Extended Part", LCSC Part Name="耐压:30V 电流:1.4A", Manufacturer="TECH PUBLIC(台舟)", Operating Temperature=-55℃~+150℃, Power Dissipation (Pd)=360mW, Reverse Transfer Capacitance (Crss@Vds)=14.8pF@15V
Q2 Q3: BOM_JLCPCB Part Class="Extended Part", BOM_Manufacturer=鑫飞宏
R1: library part R0201-10k, "Resistor, ±1%, 0.05W", Manufacturer=N.A., Part number IPS=00000001255, Part number NEMS=100100065, Part number Norautron=26107101
R2 R14 R15 R23 R24 R25 R26 R27 R28 R29 R35 R36 R37 R38 R40 SR1 SR2 SR3 SR4 SR5 SR6: library part R, "Resistor"
R3: library part R0201-1k0, "Resistor, ±1%, 0.05W", Manufacturer=N.A., Part number IPS=00000005786, Part number NEMS=100100043
R9 R10: library part R0201-1M0, "Resistor, ±1%, 0.05W", Manufacturer=N.A., Part number IPS=00000001418, Part number NEMS=100100093, Part number Norautron=26107108
R17 R18 R19 R20 R21: library part RES2
U1: "Multi-protocol Bluetooth Low Energy, ANT and 2.4GHz proprietary system-on-chip", Manufacturer="Nordic Semiconductor"
U3: library part ETA9697E8A_C7435201, Input Voltage=4.25V~6V, JLCPCB Part Class="Extended Part", LCSC Part Name=超低功耗PMU带16V线性充电器和5V升压转换器, Manufacturer=ETA(钰泰), Operating Temperature=-40℃~+85℃, Output Current=400mA, Output Voltage=5V, Quiescent Current (Iq)=-, Switching Frequency=1.4MHz
U4: Input Voltage=-, JLCPCB Part Class="Extended Part", LCSC Part Name=降压型, Manufacturer=silergy(矽力杰)
U5: library part QMA6100P_C2887190, JLCPCB Part Class="Extended Part", Manufacturer=QST(上海矽睿)
U7: JLCPCB Part Class="Extended Part", Manufacturer=FM(富满), Operating Temperature=-, Output Power=2Wx1@4Ω, Supply Voltage=2.5V~5.5V
U8: JLCPCB Part Class="Extended Part", Manufacturer=WINBOND(华邦), Operating Temperature=-40℃~+85℃, Supply Voltage=2.7V~3.6V
U9: "SIMIC;CUCC;M2MMFF2;VQFN8(6*5*0.65mm);浙江联通4G流量卡", Manufacture 1=ZJLT4GT1-L, Manufacturer=上海光曜
X1: library part XTAL_SMD2016_32MHz_8pF_General, "XTAL SMD 2016, 32MHz, Cl=8pF, Total Tol: ±40ppm"

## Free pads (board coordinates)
  round 53.15 hole 47.24: 0(2025,3014) 0(2543,2815) 0(2755,3186)

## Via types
v1: diameter 17.72, hole 11.81, Top Layer to Bottom Layer, 121 vias
v2: diameter 25.98, hole 12.99, Top Layer to Bottom Layer, 16 vias
v3: diameter 19.68, hole 11.81, Top Layer to Bottom Layer, 8 vias
v4: diameter 25.59, hole 19.68, Top Layer to Bottom Layer, 1 vias
v5: diameter 27.56, hole 19.68, Top Layer to Bottom Layer, 1 vias

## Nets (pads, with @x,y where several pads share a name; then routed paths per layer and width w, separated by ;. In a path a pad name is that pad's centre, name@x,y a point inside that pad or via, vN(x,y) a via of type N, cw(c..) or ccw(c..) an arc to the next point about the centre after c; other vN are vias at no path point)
5V_POWER: C35.1 R20.2 U2.13 | length 317.1
  Bottom Layer w10: R20.2@2399.98,3138 2399.01,3138.97 2399.01,3139.99 2390,3149 2359,3149 2349,3159 2349,3252 2364.46,3267.46 C35.1@2407,3267.46 2411.46,3263 2501.51,3263 2501.98,3262.53 U2.13@2501.98,3260.17
+5V: C45.2 C46.2 C52.2 R11.2 R24.1 U3.5 U4.4 | length 1133.7
  Top Layer w20: v5(2644,3419) 2645.45,3417.55 2685.07,3417.55 2702.62,3400 2811,3400 2830,3381 R11.2@2830,3289
  med2 w20: v4(2391,3464) 2392.07,3462.93 2392.07,3427.93 2434,3386 2611,3386 v5(2644,3419)
  Bottom Layer w10: R24.1@2173,3323.02 2173,3346.51 2178.86,3352.37 U4.4@2231.2,3352.37 2231.2,3487.2 2253.54,3509.54
  Bottom Layer w20: 2273.37,3503.92 2276.28,3501.01 2293.37,3501.01 2294,3500.38 2294,3498 2291.46,3498 C52.2@2294,3495.46 ; C52.2@2294,3493.46 C52.2@2294,3496 ; v4(2391,3464) 2390,3465 2390,3496 2419,3496 2420,3497 2460.69,3497 2478.69,3479 U3.5@2490.5,3479
  Bottom Layer w39.37: C52.2@2294,3496 2351,3496 2390,3496
AC1: C36.2 C37.2 C39.1 C40.2 C41.2 U2.16 | length 410.5
  Bottom Layer w10: U2.16@2558.92,3260.12 2603.12,3260.12 2620,3277 ; C41.2@2706,3187.46 2706,3276.46 2727.01,3276.46 2737.99,3265.49 2737.99,3258.63 2741.45,3255.17 2748.3,3255.17 2748.3,3253.24 C36.2@2748.54,3253 ; C40.2@2748.54,3364 C40.2@2749.54,3365
  Bottom Layer w19.68: 2620,3277 C39.1@2646,3277 ; C39.1@2646,3276.46 2706,3276.46
  Bottom Layer w23.62: C36.2@2748.3,3254.18 C37.2@2748.3,3307.82 ; C37.2@2748.54,3309 C40.2@2748.54,3364
AC2: C41.1 C42.1 TP3.1 U2.5 | length 425.9
  Bottom Layer w10: U2.5@2559.07,3138.72 2597.28,3138.72 2611.92,3124.08 ; TP3.1@2835.32,3115 TP3.1@2850.32,3100 ; TP3.1@2869,3100 TP3.1@2870,3100
  Bottom Layer w19.68: 2726.3,3124.08 2751.38,3099 2869,3099 TP3.1@2870,3100
  Bottom Layer w31.5: 2626.37,3124.08 2631.37,3119.08 C42.1@2647,3119.08 2721.3,3119.08 2726.3,3124.08 ; 2869,3143 2869,3100 2869,3099 2869,3061 2872,3058
ADC_POWER: R8.2 R23.2 R28.1 | length 1382.2
  Top Layer w10: R8.2@2360,3031.49 2360,2991 2374,2977 2414,2977 2453,2938 2572,2938 v1(2573,2939)
  med1 w10: v1(2573,2939) 2593,2959 2593,3090 2568,3115 2568,3185 2588,3205 2626,3205 2652,3179 2694,3179 2708,3193 2708,3386 2727,3405 2807,3405 2827,3425 2827,3597 2863,3633 v1(2916,3633)
  Bottom Layer w10: R28.1@2848,3644.49 2848.97,3643.52 2849.48,3643.52 2859.98,3633.02 R23.2@2889,3633.02 v1(2916,3633)
B_DEC2: U1.32
B_DEC3: C20.1 U1.33 | length 69.7
  Top Layer w6: C20.1@2743,2792 2744.97,2792 2778.37,2825.4 U1.33@2778.37,2845.91
B_DEC4: C12.2 U1.46 | length 40.2
  Top Layer w6: U1.46@2858.09,3020.12 2858.45,3020.47 2897.65,3020.47 C12.2@2898,3020.82
B_P0.22: U1.27
B_P0.23: U1.28
B_P0.24: U1.29
B_P0.25: U1.37
B_P0.26: U1.38
B_P0.27: U1.39
B_P0.28/AIN4: U1.40
B_P0.29/AIN5: U1.41
B_P0.30/AIN6: U1.42
B_P0.31/AIN7: U1.43
B_SWDCLK: J6.3 U1.25 | length 246.3
  Top Layer w6: v1(2561,2889) 2561,2886 2601.09,2845.91 U1.25@2652.39,2845.91
  Bottom Layer w6: J6.3@2441,2926 2472,2926 2509,2889 v1(2561,2889)
B_SWDIO: J6.2 U1.26 | length 281.8
  Top Layer w6: v1(2536,2862) 2536.86,2861.14 2553.86,2861.14 2594,2821 2664.49,2821 2668,2824.51 2668,2845.77 U1.26@2668.13,2845.91
  Bottom Layer w6: J6.2@2441,2826 2479,2826 2515,2862 v1(2536,2862)
B_XC1: C17.1 U1.34 X1.1 | length 134.7
  Top Layer w6: C17.1@2746.97,2736.82 C17.1@2745,2736.82 2747.91,2739.73 2753.61,2739.73 2788.82,2774.94 X1.1@2788.82,2776.91 2794.12,2782.2 U1.34@2794.12,2845.91
B_XC2: C13.1 U1.35 X1.3 | length 205.4
  Top Layer w6: U1.35@2809.87,2845.91 2809.87,2824.13 2824,2810 2864,2810 2881.79,2792.21 2881.79,2782.03 C13.1@2883,2780.82 2880.09,2777.92 2870.92,2777.92 2863,2770 2863,2750.69 2856.31,2744.01 2834.09,2721.79 X1.3@2834.09,2719.82
BL_P0.02/AIN0: U1.4
BL_P0.03/AIN1: U1.5
BL_P0.04/AIN2: U1.6
BL_P0.05/AIN3: U1.7
BL_P0.06: M1.6 U1.8 | length 274.7
  Top Layer w6: M1.6@2536.46,3211.4 2605.6,3211.4 2639,3178 2695,3178 2715.38,3157.62 U1.8@2715.38,3084.09
BL_P0.07: U1.9
BL_P0.08: M1.5 U1.10 | length 226.6
  Top Layer w6: M1.5@2536.46,3191.72 2605.28,3191.72 2635,3162 2665,3162 2683.88,3143.12 U1.10@2683.88,3084.09
BL_P0.09: U1.11
BL_P0.10: U1.12
BL_P0.11: U1.14
BL_P0.12: U1.15
BL_P0.13: U1.16
BL_P0.14: R4.2 U1.17 | length 36.1
  Top Layer w6: R4.2@2584,2989 2584.19,2988.81 2619.72,2988.81 U1.17@2619.91,2988.62
BL_P0.15: U1.18
BL_P0.16: U1.19
BL_P0.17: U1.20
BL_P0.18: U1.21
BL_P0.19: U1.22
BL_P0.20: U1.23
BL_P0.21: U1.24
BUSY: FPC1.15 M1.80 | length 1402.7
  Top Layer w7.87: v1(1641,3276) 1641,3278.66 1637,3282.66 1637,3305.61 1633,3309.61 1633,3365 1677.74,3409.74 FPC1.15@1753,3409.74 ; v1(2465,2963) 2503,3001 2503,3059 2502.01,3059.99 M1.80@2502.01,3098.23
  med1 w7.87: v1(1641,3276) 1641,3162 1699,3104 2123,3104 2264,2963 v1(2465,2963)
COEX0: M1.52 R9.2 | length 41
  Top Layer w7.87: R9.2@2055,3264.51 2055.41,3264.51 2061.37,3270.47 M1.52@2093.54,3270.47
COEX1: M1.53
COEX2: M1.54 R10.2 | length 54.2
  Top Layer w7.87: R10.2@2055,3204.51 2055.41,3204.51 2066,3215.1 2066,3223 2074.1,3231.1 M1.54@2093.54,3231.1
CS: FPC1.12 M1.77 | length 1012.1
  Top Layer w7.87: v1(1700,3299) 1700,3328 1722.68,3350.68 FPC1.12@1753,3350.68 ; v1(2419,3022) 2442.95,3045.95 M1.77@2442.95,3098.23
  med1 w7.87: v1(1700,3299) 1701,3300 1732,3300 1795,3237 2091,3237 2302,3026 2412.34,3026 2416.34,3022 v1(2419,3022)
D/C: FPC1.13 M1.78 | length 1202.9
  Top Layer w7.87: v1(1679,3273) 1679,3342 1707.37,3370.37 FPC1.13@1753,3370.37 ; v1(2443,2986) 2443,3019 2462.32,3038.32 2462.32,3097.91 M1.78@2462.64,3098.23
  med1 w7.87: v1(1679,3273) 1679,3202 1716,3165 2117,3165 2300,2982 2436.34,2982 2440.34,2986 v1(2443,2986)
DEC0: C10.1 M1.24 | length 63.2
  Top Layer w7.87: M1.24@2442.95,3501.77 2443.98,3502.8 C10.1@2444,3564.54
DEC1: C15.1 U1.1 | length 62.3
  Top Layer w6: C15.1@2825,3146.18 2825.31,3145.87 2825.31,3084.4 U1.1@2825.61,3084.09
EN_B: U2.11
GDR: FPC1.18 Q1.1 R14.2 | length 171
  Top Layer w7.87: FPC1.18@1753,3468.8 1754.97,3470.77 1773.77,3470.77 1809.69,3506.69 1832,3506.69 1883.09,3506.69 1894.82,3518.42 Q1.1@1894.82,3527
